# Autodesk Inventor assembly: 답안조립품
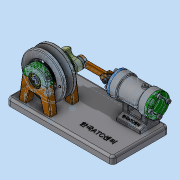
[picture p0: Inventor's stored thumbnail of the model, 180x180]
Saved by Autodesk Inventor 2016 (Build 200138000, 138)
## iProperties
Created: 2018-01
Part Number: 답안조립품
Material: 일반
Document SubType Name: Assembly
Designer: Administrator
Author: Administrator
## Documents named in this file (19)
- C:\Users\Administrator\Desktop\380107V1039\답안조립품.iam
- C:\Users\Administrator\Desktop\380107V1039\3mm 와셔.ipt
- C:\Users\Administrator\Desktop\380107V1039\V-벨트풀리.ipt
- C:\Users\Administrator\Desktop\380107V1039\둥근머리볼트 M3x12.ipt
- C:\Users\Administrator\Desktop\380107V1039\베어링 8x22x7.ipt
- C:\Users\Administrator\Desktop\380107V1039\베어링커버-A.ipt
- C:\Users\Administrator\Desktop\380107V1039\볼트 M3x8.ipt
- C:\Users\Administrator\Desktop\380107V1039\볼트 M3x12.ipt
- C:\Users\Administrator\Desktop\380107V1039\스페이서.ipt
- C:\Users\Administrator\Desktop\380107V1039\지지대-A.ipt
- C:\Users\Administrator\Desktop\380107V1039\커넥팅로드-A.ipt
- C:\Users\Administrator\Desktop\380107V1039\커넥팅로드-B.ipt
- C:\Users\Administrator\Desktop\380107V1039\크랭크축.ipt
- C:\Users\Administrator\Desktop\380107V1039\플랜지.ipt
- C:\Users\Administrator\Desktop\380107V1039\플레이트.ipt
- C:\Users\Administrator\Desktop\380107V1039\피스톤.ipt
- C:\Users\Administrator\Desktop\380107V1039\하우징.ipt
- C:\Users\Administrator\Desktop\380107V1039\하우징커버-A.ipt
- C:\Users\Administrator\Desktop\380107V1039\하우징커버-B.ipt
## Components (9 placed, 8 different names)
1. 3mm 와셔:1
2. 3mm 와셔:2
3. V-벨트풀리:1 — 각도:1, 각도:2
4. 플랜지:1
5. 플레이트:1 — 각도:2
6. 피스톤:1
7. 하우징:1
8. 하우징커버-A:1
9. 하우징커버-B:1
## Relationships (2: Angle 2)
- 각도:1 [Angle]: V-벨트풀리:1
- 각도:2 [Angle]: V-벨트풀리:1 ↔ 플레이트:1
